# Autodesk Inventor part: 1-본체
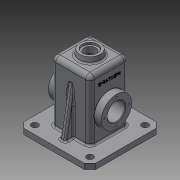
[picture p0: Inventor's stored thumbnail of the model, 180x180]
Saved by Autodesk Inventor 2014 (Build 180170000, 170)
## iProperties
Created: 2016-02
Part Number: 1-본체
Material: 일반
Document SubType Name: Modeling
Designer: 전형준
Density: 1 g/cm^3
Appearance: 기본값
Author: 전형준
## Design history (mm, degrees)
sketch "스케치2"
  geometry: L1 (65, 65)-(-65, 65); L2 (-65, 65)-(-65, -65); L3 (-65, -65)-(65, -65); L4 (65, -65)-(65, 65); 3 further points
  constraints: 8 end point, 2 midpoint, 2 parallel, 1 horizontal, 1 horizontal alignment, 1 perpendicular, 1 vertical alignment
  dimensions: "d2" = 130 distance of L1.start L1.end; "d3" = 130 distance of L3.end L1.start
extrude "돌출1" new body sketch "스케치2" distance "d4" = 10; taper "d5" = 0 deg
sketch "스케치3"
  geometry: L1 (-35, 35)-(35, 35); L2 (35, 35)-(35, -35); L3 (35, -35)-(-35, -35); L4 (-35, -35)-(-35, 35); 3 further points
  constraints: 8 end point, 2 midpoint, 2 parallel, 1 horizontal, 1 horizontal alignment, 1 perpendicular, 1 vertical alignment
  dimensions: "d6" = 70 distance of L1.start L1.end; "d7" = 70 distance of L1.end L2.end (= d6)
extrude "돌출2" join sketch "스케치3" distance "d8" = 110; taper "d9" = 0 deg
feature "쉘1" dims "d10" = 10, "d11" = 5
fillet "모깎기1" dims "d12" = 8
fillet "모깎기2" dims "d13" = 8
chamfer "모따기1" distance "d14" = 10; stored, may be unused: second distance "d15" = 2, angle "d16" = 45 deg
fillet "모깎기3" dims "d17" = 3
fillet "모깎기4" dims "d18" = 3
sketch "스케치4"
  geometry: L1 (-55, -65)-(55, -65) reference; L2 (-65, 55)-(-65, -55) reference; 2 further points
  dimensions: "d19" = 15 distance from line of L1 point (-50, -50); "d20" = 15 distance from line of L2 point (-50, -50)
hole "구멍1" sketch "스케치4" at (-50, -50) diameter "d21" = 12; stored, may be unused: countersink angle "d25" = 90 deg, drill point angle "d27" = 118 deg; dims "d22" = 6, "d23" = 4, "d24" = 2, "d26" = 8
sketch "스케치5"
  geometry: C1 r 20 at (0, 0); 1 further point
  constraints: 1 centre point, 1 coincident
  dimensions: "d34" = 40 diameter of C1
extrude "돌출3" join sketch "스케치5" distance "d35" = 10; taper "d36" = -10 deg
fillet "모깎기5" dims "d37" = 3
hole "구멍2" diameter "d40" = 21; stored, may be unused: countersink angle "d44" = 90 deg, drill point angle "d46" = 118 deg; dims "d38" = 10, "d39" = 10, "d41" = 6, "d42" = 28, "d43" = 4, "d45" = 8
sketch "스케치6"
  geometry: L1 (10, -28)-(10, 82) reference; C1 r 27.5 at (-45, 27); 2 further points
  constraints: 1 centre point, 1 horizontal alignment, 1 midpoint
  dimensions: "d47" = 55 diameter of C1; "d48" = 55 distance from line of C1.centre L1
extrude "돌출4" join sketch "스케치6" distance "d49" = 13; taper "d50" = 0 deg
fillet "모깎기6" dims "d51" = 0.5
sketch "스케치9"
  geometry: C1 r 27.5 at (55, 27) reference; C2 r 27.5 at (55, 27); 1 further point
  constraints: 1 centre point, 1 coincident, 1 concentric
  dimensions: "d52" = 55 diameter of C2 (derived)
extrude "돌출5" join sketch "스케치9" distance "d53" = 7; taper "d54" = -45 deg
sketch "스케치10" dims "d55" = 45
  geometry: C1 r 27.5 at (0, 0) reference; 3 further points
  constraints: 2 vertical alignment, 1 coincident, 2 other
hole "구멍3" sketch "스케치10" at (0, 22.5) diameter "d56" = 3.242; stored, may be unused: countersink angle "d60" = 90 deg, drill point angle "d62" = 118 deg; dims "d57" = 8, "d58" = 28, "d59" = 4, "d61" = 10
hole "구멍4" diameter "d69" = 32; stored, may be unused: countersink angle "d73" = 90 deg, drill point angle "d75" = 0 deg; dims "d67" = 10, "d68" = 10, "d70" = 8, "d71" = 28, "d72" = 4, "d74" = 10
chamfer "모따기2" distance "d76" = 1; stored, may be unused: second distance "d77" = 2, angle "d78" = 45 deg
fillet "모깎기8" dims "d79" = 0.5
fillet "모깎기9" dims "d80" = 0.5
sketch "스케치11"
  geometry: L1 (65, 10)-(65, 0) reference; L2 (50, 10)-(50, 0); L3 (50, 10)-(35, 95.069); L4 (35, 112)-(35, 10) reference; L5 (44, 10)-(56, 10) reference; L6 (55, 10)-(65, 10) reference; L7 (55, 10)-(-55, 10) reference; 1 further point
  constraints: 4 end point, 1 midpoint, 1 parallel, 1 point on line
  dimensions: "d81" = 15 distance between parallel lines of L2 L1; "d82" = 10 deg angle of L3 L2
feature "리브1" sketch "스케치11" dims "d83" = 1, "d84" = 10, "d85" = 0, "d86" = 0, "d87" = 1, "d88" = 1
fillet "모깎기15" dims "d94" = 3
fillet "모깎기16" dims "d95" = 3
fillet "모깎기17" dims "d96" = 3
sketch "스케치12"
  geometry: L1 (5.57, 6.261)-(5.57, 47.739); L2 (5.57, 47.739)-(18.43, 47.739); L3 (18.43, 47.739)-(18.43, 6.261); L4 (18.43, 6.261)-(5.57, 6.261); L5 (112, -28)-(112, 82) reference; L6 (-18, 8.763)-(-18, 45.237) reference; L7 (0, -8)-(99, -8) reference; 5 further points
  constraints: 3 midpoint, 2 horizontal alignment, 1 parallel, 1 vertical alignment, 2 other
  dimensions: "d97" = 30 distance from line of point (12, 27) L6; "d98" = 35 distance from line of L7 point (12, 27) (derived)
feature "엠보싱1" sketch "스케치12" dims "d2" = 130, "d3" = 130, "d12" = 8, "d99" = 0.5, "d100" = 0
node "솔리드1"
pattern_linear "직사각형 패턴1" dims "d30" = 100
pattern_circular "원형 패턴1" dims angle "d64" = 360 deg
mirror "대칭2"
mirror "대칭3"
node "투영된 루프1"
